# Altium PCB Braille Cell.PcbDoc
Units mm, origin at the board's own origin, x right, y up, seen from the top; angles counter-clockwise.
Board outline 7.72 x 29.64 mm, 2 copper layers (Top, Bottom); 1 components, 12 nets, 22 pads, 15 vias.
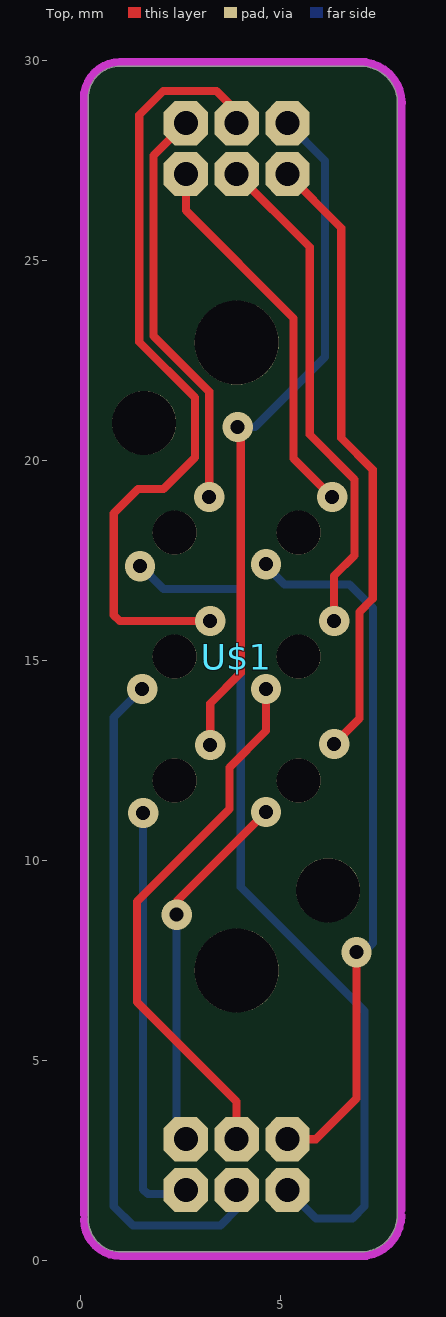
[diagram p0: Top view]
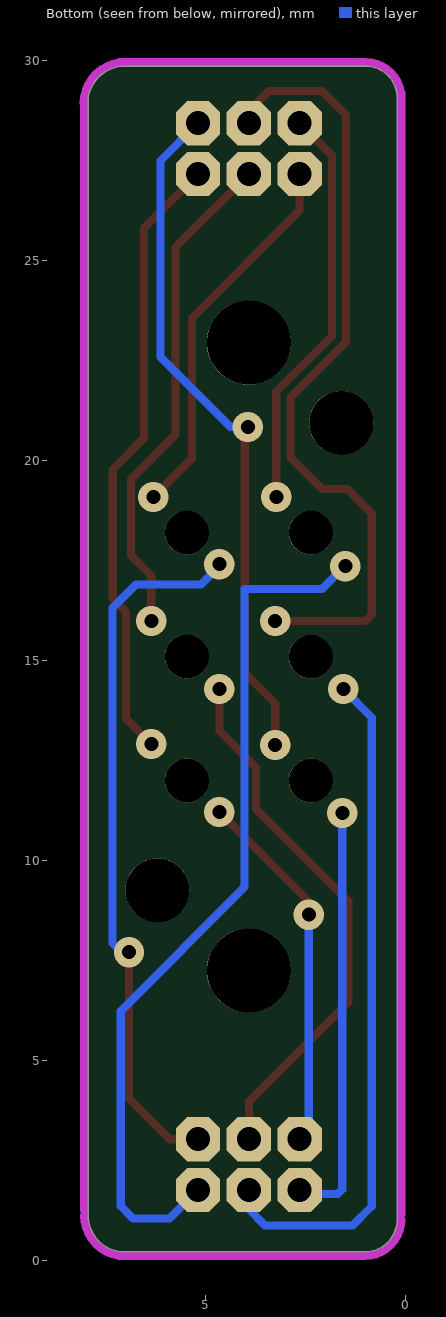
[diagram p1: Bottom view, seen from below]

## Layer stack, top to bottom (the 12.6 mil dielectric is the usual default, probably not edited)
Top Solder: solder mask 0.0102, Solder Resist, Dk 3.5
Top: signal copper 0.035
Dielectric 1: dielectric 0.32, FR-4, Dk 4.8
Bottom: signal copper 0.035
Bottom Solder: solder mask 0.0102, Solder Resist, Dk 3.5

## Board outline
0.204,1.016 0.204,29.058 cw(c0.991,29.058) 0.991,29.845 7.023,29.845 cw(c7.011,28.918) 7.924,29.072 7.924,1.117 cw(c7.01,1.117) 7.037,0.204 1.022,0.204 1.016,0.204 cw(c1.016,1.016)

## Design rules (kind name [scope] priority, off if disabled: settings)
BoardOutlineClearance [All] p1: gap=0.5 ignorepadtopadclearanceinfootprint=FALSE
BoardOutlineClearance mdCopperDimension [All] p2: gap=0.2 ignorepadtopadclearanceinfootprint=FALSE
Clearance "Clearance (Same Net)" [All] p1: gap=0.152 ignorepadtopadclearanceinfootprint=FALSE
Clearance [All] p2: gap=0.127 ignorepadtopadclearanceinfootprint=FALSE
HoleSize [All] p1: absolutevalues=TRUE maxlimit=2540 minlimit=0.3 maxpercent=80.000 minpercent=20.000
HoleToHoleClearance mdDrill [All] p1: gap=0.152 allowstackedmicrovias=TRUE
MinimumAnnularRing [All] p1: minimumring=0.18
MinimumSolderMaskSliver [All] p1 off: minsoldermaskwidth=0.254
PasteMaskExpansion mlMinCreamFrame [All] p1: expansion=0
PolygonConnect ThermalVias [IsVia] p1: connectstyle=Direct reliefconductorwidth=0.254 reliefentries=4 polygonreliefangle="90 Angle" airgapwidth=0.254
PolygonConnect [All] p2: connectstyle=Relief reliefconductorwidth=0.254 reliefentries=4 polygonreliefangle="90 Angle" airgapwidth=0.254
RoutingVias [All] p1: holewidth=0.3 width=0.7 viastyle="Through Hole" minholewidth=0.18 minwidth=0.6 maxholewidth=2.54 maxwidth=2.54
ShortCircuit [All] p1: allowed=TRUE
SolderMaskExpansion mlMinStopFrame [All] p1: expansion=0.102 istentingtop=FALSE
SupplyNets "Schematic Supply Nets_13" [InNet('GND')] p1: voltage=0.000
SupplyNets "Schematic Supply Nets_12" [InNet('VFB1')] p2: voltage=0.000
SupplyNets "Schematic Supply Nets_11" [InNet('VEN_Buck')] p3: voltage=0.000
SupplyNets "Schematic Supply Nets_10" [InNet('VPG2')] p4: voltage=0.000
SupplyNets "Schematic Supply Nets_9" [InNet('VFB2')] p5: voltage=0.000
SupplyNets "Schematic Supply Nets_8" [InNet('VCC1')] p6: voltage=0.000
SupplyNets "Schematic Supply Nets_7" [InNet('VSW1')] p7: voltage=0.000
SupplyNets "Schematic Supply Nets_6" [InNet('V_Drive')] p8: voltage=0.000
SupplyNets "Schematic Supply Nets_5" [InNet('VSW2')] p9: voltage=0.000
SupplyNets "Schematic Supply Nets_4" [InNet('VCC_Filtered')] p10: voltage=0.000
SupplyNets "Schematic Supply Nets_3" [InNet('VPG1')] p11: voltage=0.000
SupplyNets "Schematic Supply Nets_2" [InNet('Vin')] p12: voltage=0.000
SupplyNets "Schematic Supply Nets_1" [InNet('V_Drive1')] p13: voltage=0.000
SupplyNets "Schematic Supply Nets" [InNet('VCC')] p14: voltage=0.000
UnRoutedNet [All] p1 off:
Width [All] p1: maxlimit=0.254 minlimit=0.127 preferedwidth=0.127 minimp=50.000000 maximp=50.000000 favimp=50.000000
24 further rules are at their usual default settings.

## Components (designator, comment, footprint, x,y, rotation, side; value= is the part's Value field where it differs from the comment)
U$1 "BRAILLE-6" BRAILLE-6 3.912,15.088 r0 top

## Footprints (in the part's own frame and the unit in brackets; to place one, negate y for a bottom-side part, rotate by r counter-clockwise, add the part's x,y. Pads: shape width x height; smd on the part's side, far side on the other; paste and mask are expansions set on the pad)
BRAILLE-6 [mm] "BRAILLE-6"
  oct 1.108x1.108 / inner round 1.024 / far side oct 1.108x1.108 hole 0.6: P$1(-1.27,13.335) P$2(1.27,-13.335) P$3(0,13.335) P$4(0,-13.335) P$5(1.27,13.335) P$6(-1.27,-13.335) P$7(-1.27,12.065) P$8(1.27,-12.065) P$9(0,12.065) P$10(0,-12.065) P$11(1.27,12.065) P$12(-1.27,-12.065)
  body extent -1.79,-13.86 1.79,13.86, height 1.27

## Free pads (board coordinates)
  round 1.1 hole 1.1 unplated: MH1(2.362,18.186) MH2(5.461,18.186) MH3(2.362,15.088) MH4(5.461,15.088) MH5(2.362,11.989) MH6(5.461,11.989)
  round 2.1 hole 2.1 unplated: MH7(3.912,22.936) MH8(3.912,7.239)
  round 1.6 hole 1.6 unplated: MH9(1.6,20.93) MH10(6.198,9.246)

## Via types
v1: diameter 0.756/0.756 (per signal layer), hole 0.35, Top to Bottom, 15 vias

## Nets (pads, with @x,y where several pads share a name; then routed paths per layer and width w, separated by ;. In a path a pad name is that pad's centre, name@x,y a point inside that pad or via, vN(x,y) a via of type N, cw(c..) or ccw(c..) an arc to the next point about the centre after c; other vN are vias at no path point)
1A: 
1B: 
2A: 
2B: 
3A: 
3B: 
4A: 
4B: 
5A: 
5B: 
6A: 
6B: 
pads on no net: U$1.P$1 U$1.P$2 U$1.P$3 U$1.P$4 U$1.P$5 U$1.P$6 U$1.P$7 U$1.P$8 U$1.P$9 U$1.P$10 U$1.P$11 U$1.P$12
copper on no net: | length 176
  Top w0.203: v1(2.413,8.636) 2.413,8.966 v1(4.648,11.201) ; 2.642,27.153 2.642,26.238 5.334,23.546 5.334,20.041 v1(6.299,19.075) ; 2.642,28.423 1.834,27.615 1.834,23.103 3.226,21.711 v1(3.226,19.075) ; v1(3.251,12.878) 3.251,13.919 4.013,14.681 4.013,20.752 v1(3.937,20.828) ; v1(3.251,15.977) 0.991,15.977 0.838,16.129 0.838,18.669 1.448,19.279 2.083,19.279 2.87,20.066 2.87,21.563 1.478,22.956 1.478,28.631 2.078,29.231 3.408,29.231 3.912,28.727 3.912,28.423 ; 3.912,3.023 3.912,3.962 1.422,6.452 1.422,8.966 3.734,11.278 3.734,12.319 4.648,13.233 v1(4.648,14.275) ; 3.912,27.153 5.74,25.324 5.74,20.635 6.858,19.518 6.858,17.617 6.35,17.109 v1(6.35,15.977) ; 5.182,3.023 5.893,3.023 6.909,4.039 v1(6.909,7.696) ; 5.182,27.153 6.528,25.806 6.528,20.554 7.313,19.769 7.313,16.533 6.985,16.205 6.985,13.538 v1(6.35,12.903) ; 5.182,28.423 5.309,28.423
  Bottom w0.203: v1(1.499,17.348) 1.513,17.348 2.086,16.776 4.015,16.776 4.015,9.326 7.112,6.23 7.112,1.346 6.807,1.041 5.893,1.041 5.182,1.753 ; v1(1.549,14.275) 0.838,13.564 0.838,1.346 1.321,0.864 3.505,0.864 3.912,1.27 3.912,1.753 ; v1(1.575,11.176) 1.575,8.611 1.575,1.767 1.694,1.648 2.537,1.648 2.642,1.753 ; v1(2.413,8.636) 2.413,3.251 2.642,3.023 ; v1@3.683,20.828 v1(3.937,20.828) 4.369,20.828 6.121,22.581 6.121,27.483 5.182,28.423 ; v1(4.648,17.399) 4.648,17.348 5.105,16.891 6.731,16.891 7.319,16.303 7.319,7.925 7.09,7.696 v1(6.909,7.696)

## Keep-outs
Keep-Out Layer:
  lines w0.203: 0.102,1.016 ccw(c1.016,1.016) 1.016,0.102 7.163,0.101 ; 0.102,1.143 0.102,29.185 ; 0.102,29.058 cw(c0.991,29.058) 0.991,29.947 7.138,29.947 ; 6.998,29.947 cw(c7.011,28.918) 8.039,28.931 ; 7.011,0.101 ccw(c7.011,1.117) 8.027,1.117 ; 8.026,1.245 8.026,28.931

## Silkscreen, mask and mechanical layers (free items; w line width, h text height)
Dimension:
  lines w0.203: 6.998,29.947 cw(c7.011,28.918) 8.039,28.931 ; 7.01,0.101 ccw(c7.01,1.117) 8.026,1.117 8.026,29.16 ; 7.138,29.947 0.991,29.947 ccw(c0.991,29.058) 0.102,29.058 0.102,1.016 ccw(c1.016,1.016) 1.016,0.102 7.163,0.102
Top 3D Body:
  text "These are the Braille cell PCB modules" at 10.685,23.889 h1.52
  text "(designed by Vijay Varada)" at 10.685,20.409 h1.52
  text "that the braille cells are soldered" at 10.685,16.802 h1.52
  text "onto so they can interface with" at 10.685,13.678 h1.52
  text "our braille reader PCB" at 10.685,10.071 h1.52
